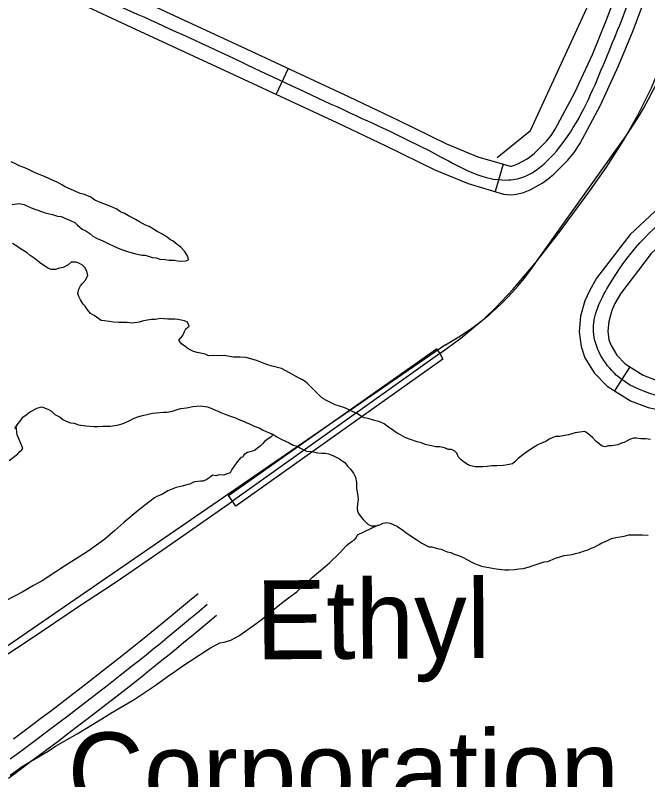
# Model space of a CAD drawing. Extents: x 3313442 to 3351311, y 721974 to 747360.
# Drawn here: x 3328533 to 3329198, y 728471 to 729274 of the extents above; entities that cross this region are included whole.
import ezdxf

# ---------------------------------------------------------------- set-up
doc = ezdxf.new("R2010")
doc.units = 0
for name, color, linetype in [('V-BLDG-IDEN', 7, 'Continuous'), ('V-BRDG-OTLN', 7, 'Continuous'), ('V-RAIL-TRAK', 7, 'Continuous'), ('V-ROAD-CNTR', 7, 'Continuous'), ('V-SITE-VEGE', 7, 'Continuous'), ('V-TOPO-SHOR', 7, 'Continuous')]:
    doc.layers.add(name, color=color, linetype=linetype)

msp = doc.modelspace()

# ---------------------------------------------------------------- linework, layer by layer
at = {"layer": 'V-BRDG-OTLN'}
msp.add_lwpolyline([(3328982.32, 728913.09), (3328764.87, 728758.35), (3328761.23, 728763.75), (3328757.11, 728769.52), (3328975.68, 728923.94), (3328979.32, 728918.99)], close=True, dxfattribs=at)
at = {"layer": 'V-RAIL-TRAK'}
msp.add_line((3328979.32, 728918.99), (3328761.23, 728763.76), dxfattribs=at)
for points in [[(3328979.32, 728918.99), (3329001.39, 728935.07), (3329016.57, 728947.61), (3329026.16, 728955.57), (3329038.06, 728967.39), (3329056.17, 728986.33), (3329079.87, 729014.34), (3329104.91, 729046.21), (3329137.15, 729090.04), (3329154.66, 729114.92), (3329172.31, 729142.82), (3329187.53, 729169.28), (3329201.92, 729198.04), (3329216.08, 729232.01), (3329229.4, 729270.58), (3329238.48, 729303.6)], [(3327828.49, 728090.38), (3327880.11, 728140.68), (3327961.34, 728211.22), (3327997.87, 728239.9), (3328025.79, 728262.33), (3328078.35, 728301.49), (3328164.14, 728361.84), (3328246.28, 728417.49), (3328326.61, 728470.48), (3328417.12, 728530.69), (3328505.94, 728590.8), (3328547.31, 728617.89), (3328600.33, 728653.66), (3328634.67, 728676.18), (3328652.15, 728687.99), (3328697.41, 728719.18), (3328761.23, 728763.76)]]:
    msp.add_lwpolyline(points, dxfattribs=at)
at = {"layer": 'V-ROAD-CNTR'}
for p, q in [((3328819.87, 729218.56), (3328807.25, 729191.35)), ((3329045.96, 729117.85), (3329037.42, 729089.09)), ((3329179.12, 728905.03), (3329163.16, 728879.63))]:
    msp.add_line(p, q, dxfattribs=at)
for points in [[(3328667.4, 729289.29), (3328775.65, 729239.08), (3328883.97, 729188.82), (3328935.41, 729164.18), (3328986.34, 729139.45), (3329019.31, 729125.76), (3329052.11, 729116.03), (3329053.78, 729115.86), (3329054.63, 729115.95), (3329057.88, 729116.8), (3329061.42, 729118.23), (3329071.11, 729123.45), (3329074.94, 729126.15), (3329078.84, 729129.43), (3329091.37, 729141.93), (3329096.31, 729148), (3329100.7, 729154.68), (3329121.32, 729193.34), (3329139.7, 729233.35), (3329154.59, 729269.47), (3329168.32, 729306.11)], [(3328598.87, 729287.96), (3328654.78, 729262.07), (3328763.02, 729211.87), (3328871.18, 729161.69), (3328922.38, 729137.16), (3328974.03, 729112.08), (3329009.26, 729097.45), (3329046.32, 729086.45), (3329053.82, 729085.71), (3329060, 729086.34), (3329067.35, 729088.28), (3329074.18, 729091.03), (3329086.91, 729097.89), (3329093.27, 729102.36), (3329099.13, 729107.3), (3329113.66, 729121.78), (3329120.55, 729130.25), (3329126.53, 729139.36), (3329148.21, 729180.01), (3329167.21, 729221.37), (3329182.51, 729258.49), (3329196.67, 729296.26)], [(3329081.07, 729015.7), (3329176.08, 729148.58)], [(3329293.2, 729122.75), (3329274.41, 729115.57), (3329247.16, 729101.4), (3329221.13, 729083.02), (3329179.4, 729044.06), (3329144.21, 728998.14), (3329136.56, 728984.84), (3329131.89, 728974.12), (3329127.33, 728958.11), (3329125.84, 728941.56), (3329127.89, 728926.32), (3329131.98, 728914.44), (3329141.45, 728898.63), (3329155.45, 728884.48), (3329179.68, 728869.25), (3329198.43, 728862.13), (3329224.9, 728856.49), (3329251.22, 728852.87), (3329323.89, 728846.16), (3329394.9, 728837.09), (3329432.04, 728828.42), (3329470.12, 728819.7), (3329513.88, 728810.63), (3329546.62, 728804.19)], [(3329303.92, 729094.73), (3329286.73, 729088.16), (3329262.81, 729075.72), (3329240.1, 729059.69), (3329201.7, 729023.84), (3329169.23, 728981.47), (3329163.4, 728971.32), (3329160.19, 728963.96), (3329156.95, 728952.61), (3329156.02, 728942.23), (3329157.22, 728933.28), (3329159.33, 728927.17), (3329165.32, 728917.15), (3329174.34, 728908.03), (3329193.11, 728896.24), (3329206.93, 728891), (3329230.07, 728886.06), (3329254.64, 728882.69), (3329327.17, 728875.99), (3329400.23, 728866.65), (3329438.8, 728857.65), (3329476.51, 728849.01), (3329519.82, 728840.04), (3329555.49, 728833.02)], [(3328985.23, 728928.08), (3327978.22, 728235.84)], [(3328725.08, 728666.38), (3328716.22, 728658.91), (3328707.62, 728651.72), (3328699.27, 728644.79), (3328691.16, 728638.11), (3328683.28, 728631.66), (3328675.63, 728625.43), (3328668.2, 728619.42), (3328660.99, 728613.62), (3328653.98, 728608.02), (3328647.19, 728602.61), (3328633.98, 728592.17), (3328621.56, 728582.43), (3328609.88, 728573.35), (3328598.89, 728564.87), (3328588.58, 728556.95), (3328578.88, 728549.55), (3328569.77, 728542.64), (3328561.22, 728536.18), (3328545.14, 728524.09), (3328531.04, 728513.56)], [(3328734.75, 728654.91), (3328725.86, 728647.42), (3328717.22, 728640.2), (3328708.83, 728633.23), (3328700.68, 728626.52), (3328692.76, 728620.04), (3328685.08, 728613.78), (3328677.62, 728607.75), (3328670.37, 728601.92), (3328663.34, 728596.29), (3328656.51, 728590.86), (3328643.26, 728580.38), (3328630.79, 728570.61), (3328619.06, 728561.49), (3328608.04, 728552.99), (3328597.69, 728545.04), (3328587.97, 728537.62), (3328578.83, 728530.68), (3328570.25, 728524.2), (3328554.14, 728512.08), (3328540, 728501.53), (3328527.6, 728492.33)], [(3328744.41, 728643.44), (3328735.5, 728635.93), (3328726.82, 728628.67), (3328718.39, 728621.67), (3328710.2, 728614.93), (3328702.25, 728608.42), (3328694.53, 728602.13), (3328687.03, 728596.07), (3328679.76, 728590.22), (3328672.7, 728584.57), (3328665.84, 728579.11), (3328652.53, 728568.59), (3328640.02, 728558.79), (3328628.25, 728549.64), (3328617.19, 728541.1), (3328606.81, 728533.13), (3328597.05, 728525.68), (3328587.89, 728518.72), (3328579.28, 728512.22), (3328563.13, 728500.08), (3328548.96, 728489.5), (3328536.53, 728480.28), (3328525.64, 728472.23)]]:
    msp.add_lwpolyline(points, dxfattribs=at)
for centre, radius, start, end in [((3328761.59, 729424.13), 497.73, 326.38346, 346.54947), ((3328854.96, 729166.81), 271.96, 298.62078, 326.24591)]:
    msp.add_arc(centre, radius, start, end, dxfattribs=at)
for points in [[(3326478.04, 730210.35), (3326482.35, 730403.29), (3326476.58, 730549.39), (3326473.61, 730637.71), (3326464.08, 730712.16), (3326370.96, 730713.71), (3326297.71, 730698.23), (3326169.71, 730725.9), (3326116.45, 730727.88), (3325982.64, 730689.67), (3325835.77, 730656.61), (3325666.24, 730661.4), (3325490.23, 730637.83), (3325403.5, 730634.84), (3325340.74, 730586.21), (3325201.43, 730523.99), (3325133.39, 730524.77), (3325012.9, 730513.46), (3324963.14, 730471.34), (3324981.93, 730365.88), (3324989.76, 730188.11), (3325009.72, 730055.84), (3325043.42, 729962.4), (3324997.98, 729812.51), (3325023.28, 729696.25), (3325064.51, 729608.4), (3325131.37, 729516.61), (3325150.36, 729377.77), (3325146.87, 729245.63), (3325126.45, 729132.53), (3325181.34, 729069.88), (3325338.87, 729062.31), (3325343.56, 728961.08), (3325372.85, 728878.06), (3325434.63, 728797.89), (3325537.34, 728748.77), (3325622.45, 728705.03), (3325714.6, 728675.45), (3325802.67, 728663.42), (3325976.26, 728695.07), (3326194.29, 728726.31), (3326466.63, 728765.32), (3326625.11, 728781.99), (3326781.78, 728849.74), (3326900.23, 728862.4), (3326981.75, 728872.83), (3327122.94, 728906.43), (3327349.99, 728934.63), (3327499.05, 728974.33), (3327515.65, 728986.69), (3327498, 729057.12), (3327490.77, 729119.3), (3327510.96, 729180.47), (3327588.76, 729283.84), (3327686.92, 729357.21), (3327753.03, 729377.43), (3327803.43, 729380.44), (3327847.87, 729388.87), (3327934.83, 729389.79), (3328039.14, 729390.23), (3328120.59, 729395.25), (3328249.21, 729403.96), (3328319.73, 729407.13), (3328384.24, 729401.49), (3328424.57, 729387.35), (3328470.08, 729368.59), (3328549.26, 729327.46), (3328661.09, 729275.68), (3328877.57, 729175.26), (3328980.19, 729125.77), (3329049.22, 729101.24), (3329067.8, 729104.63), (3329088.99, 729118.36), (3329113.61, 729147.02), (3329153.45, 729227.36), (3329182.49, 729301.19), (3329201.64, 729378.5), (3329199.66, 729471.18), (3329192.73, 729551.54), (3329166.92, 729646.66), (3329121.79, 729727.55), (3329091.49, 729778.71), (3329016.19, 729835.66), (3328941.73, 729880.13), (3328875.38, 729924.2), (3328789.67, 729967.9), (3328700.81, 730000.01), (3328643.56, 730009.51), (3328577.01, 730014.29), (3328435.19, 729993.91), (3328288.99, 729968.49), (3328169.46, 729944.48), (3328087.81, 729917.23), (3328042.9, 729880.41), (3327999.54, 729814.48), (3327967.22, 729727.08), (3328009.37, 729621.12)], [(3329560.48, 728816.75), (3329473.31, 728834.35), (3329397.56, 728851.87), (3329252.93, 728867.78), (3329164.89, 728896.25), (3329140.93, 728941.89), (3329156.72, 728989.8), (3329230.61, 729071.35), (3329298.56, 729108.74)]]:
    msp.add_spline(points, degree=3, dxfattribs=at)
at = {"layer": 'V-SITE-VEGE'}
for points in [[(3328535.25, 728813.2), (3328537.7, 728815.97), (3328539.44, 728817.36), (3328540.84, 728819.09), (3328539.81, 728821.88), (3328534.97, 728833.38), (3328533.8, 728842.32), (3328535.74, 728845.21), (3328539.16, 728849.17), (3328540.87, 728852), (3328544.28, 728854.26), (3328547.7, 728857.08), (3328550.54, 728858.78), (3328555.65, 728861.59), (3328560.76, 728862.71), (3328567, 728860.42), (3328570.96, 728858.14), (3328574.35, 728854.72), (3328580.02, 728851.87), (3328582.85, 728849.59), (3328586.24, 728847.87), (3328590.78, 728846.16), (3328594.75, 728845.58), (3328599.28, 728843.86), (3328607.22, 728842.7), (3328615.73, 728842.1), (3328619.7, 728842.09), (3328624.81, 728842.63), (3328629.34, 728842.62), (3328632.75, 728842.61), (3328640.13, 728843.72), (3328645.24, 728844.83), (3328652.62, 728848.21), (3328657.17, 728850.47), (3328661.71, 728852.15), (3328665.12, 728853.28), (3328672.5, 728854.95), (3328677.04, 728856.07), (3328681.02, 728856.62), (3328688.4, 728857.17), (3328692.37, 728857.16), (3328698.05, 728858.27), (3328703.16, 728859.95), (3328707.13, 728861.07), (3328712.81, 728861.62), (3328719.62, 728863.3), (3328727.56, 728863.84), (3328734.94, 728862.68), (3328739.47, 728860.96), (3328742.3, 728859.82), (3328746.27, 728858.1), (3328749.1, 728856.96), (3328754.2, 728854.67), (3328759.3, 728852.95), (3328764.4, 728851.23), (3328767.8, 728849.52), (3328773.46, 728847.23), (3328776.3, 728846.08), (3328779.13, 728844.94), (3328784.23, 728842.65), (3328789.89, 728840.36), (3328792.72, 728838.65), (3328797.25, 728836.37), (3328801.79, 728834.65), (3328802.4, 728834.4)], [(3328802.4, 728834.4), (3328803.29, 728832.6), (3328801.84, 728831.42), (3328795.21, 728826.57), (3328792.77, 728823.8), (3328790.32, 728821.37), (3328784.39, 728816.87), (3328777.08, 728814.8), (3328773.24, 728812.38), (3328772.19, 728809.95), (3328770.1, 728809.61), (3328766.26, 728805.1), (3328760.66, 728796.77), (3328758.91, 728793.29), (3328754.73, 728791.92), (3328752.29, 728790.88), (3328747.42, 728791.25), (3328743.94, 728790.21), (3328740.46, 728790.92), (3328734.18, 728786.42), (3328730.35, 728784.69), (3328727.91, 728784.7), (3328721.3, 728784.03), (3328718.86, 728782.99), (3328716.42, 728781.61), (3328714.33, 728781.27), (3328708.41, 728779.55), (3328702.14, 728778.18), (3328693.43, 728774.38), (3328687.85, 728770.92), (3328681.58, 728768.51), (3328679.14, 728767.12), (3328665.54, 728756.73), (3328662.05, 728753.96), (3328647.04, 728741.14), (3328637.62, 728732.82), (3328627.15, 728723.81), (3328609.36, 728711), (3328585.65, 728696.12), (3328575.53, 728689.54), (3328561.23, 728679.85), (3328552.17, 728675.01), (3328539.97, 728668.09), (3328524.63, 728659.79)], [(3328526.53, 728806.27), (3328535.25, 728813.2)], [(3328527.49, 728475.5), (3328540.05, 728484.85), (3328548.77, 728490.04), (3328567.59, 728500.76), (3328575.27, 728505.95), (3328597.93, 728519.1), (3328623.73, 728535.02), (3328633.49, 728540.9), (3328657.9, 728555.08), (3328671.5, 728564.43), (3328679.87, 728569.96), (3328692.78, 728579.31), (3328700.8, 728584.51), (3328709.17, 728590.39), (3328734.28, 728607.01), (3328738.11, 728609.43), (3328747.87, 728614.62), (3328752.4, 728615.3), (3328759.71, 728617.71), (3328768.08, 728622.2), (3328783.43, 728632.94), (3328792.84, 728639.86), (3328809.24, 728653.72), (3328820.06, 728662.04), (3328828.78, 728668.27), (3328831.22, 728670.35), (3328838.2, 728676.59), (3328845.18, 728683.52), (3328858.45, 728694.61), (3328863.33, 728698.77), (3328873.8, 728708.82), (3328877.3, 728712.99), (3328880.79, 728716.8), (3328883.23, 728718.88), (3328887.07, 728721.65), (3328889.51, 728723.04), (3328891.26, 728725.12), (3328892.66, 728728.24), (3328914.05, 728738.38), (3328916.06, 728738.94), (3328919.47, 728740.63), (3328923.44, 728741.19), (3328926.84, 728740.61), (3328929.68, 728739.46), (3328934.78, 728737.18), (3328940.44, 728733.19), (3328944.96, 728729.77), (3328947.79, 728728.05), (3328952.32, 728724.64), (3328955.15, 728722.92), (3328960.25, 728719.5), (3328967.6, 728715.51), (3328971.01, 728715.49), (3328976.68, 728713.77), (3328980.65, 728713.19), (3328986.88, 728710.33), (3328990.85, 728709.75), (3328994.25, 728708.04), (3328999.91, 728706.32), (3329003.88, 728704.6), (3329007.84, 728702.32), (3329012.37, 728700.03), (3329015.2, 728698.32), (3329018.6, 728697.17), (3329023.14, 728695.45), (3329032.77, 728693.72), (3329038.44, 728692.57), (3329047.52, 728691.4), (3329052.06, 728691.38), (3329058.3, 728691.93), (3329062.27, 728692.48), (3329066.81, 728693.03), (3329073.62, 728694.71), (3329076.47, 728695.84), (3329081.58, 728697.53), (3329088.96, 728699.77), (3329092.94, 728700.32), (3329100.89, 728703.7), (3329104.3, 728704.82), (3329109.98, 728706.5), (3329113.38, 728707.06), (3329118.49, 728707.61), (3329121.9, 728708.73), (3329126.44, 728709.85), (3329130.42, 728710.97), (3329134.96, 728712.66), (3329138.37, 728714.35), (3329141.78, 728715.47), (3329146.32, 728717.72), (3329149.74, 728719.98)], [(3329149.74, 728719.98), (3329154.28, 728721.67), (3329159.97, 728724.48), (3329164.51, 728725.6), (3329173.02, 728726.71), (3329178.13, 728728.4), (3329187.21, 728728.36), (3329192.32, 728728.35), (3329198.55, 728727.76)]]:
    msp.add_lwpolyline(points, dxfattribs=at)
at = {"layer": 'V-TOPO-SHOR'}
for points in [[(3329039.46, 729124.75), (3329074.8, 729153.34), (3329149.99, 729317.31), (3329162.14, 729386.82), (3329162.17, 729468.71), (3329151.85, 729553.02), (3329129.91, 729616.84), (3329086.32, 729704.83), (3329043.63, 729755.76), (3329008.26, 729791.33), (3328964.31, 729819.35), (3328917.76, 729847.97), (3328807.16, 729912.04), (3328690.73, 729957), (3328640.55, 729970.09), (3328595.12, 729968.43), (3328531.35, 729964.23), (3328419.34, 729952.19), (3328207.43, 729915.73), (3328162.39, 729909.87)], [(3328699.07, 729036.81), (3328696.24, 729038.52), (3328692.85, 729040.8), (3328687.75, 729044.22), (3328682.09, 729047.08), (3328679.26, 729048.79), (3328673.6, 729052.21), (3328669.63, 729053.93), (3328663.4, 729057.35), (3328659.44, 729059.64), (3328652.08, 729063.63), (3328647.55, 729065.92), (3328643.58, 729067.63), (3328639.62, 729070.48), (3328633.39, 729073.34), (3328628.86, 729075.06), (3328623.19, 729077.35), (3328616.39, 729080.21), (3328612.43, 729083.06), (3328605.63, 729085.92), (3328601.1, 729087.07), (3328594.87, 729089.93), (3328590.9, 729091.65), (3328585.24, 729093.93), (3328581.84, 729096.21), (3328576.74, 729099.07), (3328572.78, 729100.79), (3328568.81, 729102.5), (3328563.71, 729104.79), (3328556.35, 729107.65), (3328552.38, 729109.36), (3328546.72, 729112.22), (3328542.75, 729113.94), (3328537.09, 729116.22), (3328533.69, 729117.94), (3328528.59, 729120.23)], [(3328529.57, 729075.4), (3328536.95, 729076.51), (3328542.05, 729075.36), (3328549.42, 729071.93), (3328554.52, 729070.21), (3328561.32, 729067.92), (3328564.15, 729066.77), (3328568.68, 729065.62), (3328572.08, 729065.05), (3328577.19, 729063.33), (3328581.16, 729062.74), (3328586.82, 729060.46), (3328590.79, 729058.74), (3328595.32, 729056.45), (3328598.15, 729053.61), (3328603.24, 729049.62), (3328607.2, 729047.9), (3328611.16, 729045.05), (3328614.56, 729042.2), (3328619.65, 729039.35), (3328624.19, 729037.63), (3328629.85, 729034.78), (3328637.21, 729031.35), (3328642.88, 729029.06), (3328645.71, 729027.91), (3328650.81, 729026.2), (3328654.21, 729025.05), (3328658.18, 729023.9), (3328666.12, 729022.17), (3328669.52, 729022.16), (3328674.06, 729021.01), (3328676.89, 729019.86), (3328680.86, 729019.28), (3328684.83, 729018.13), (3328690.5, 729017.55), (3328694.47, 729016.97), (3328700.14, 729016.95), (3328703.54, 729016.37), (3328708.08, 729015.79), (3328712.05, 729016.34), (3328714.89, 729017.46), (3328714.33, 729020.87), (3328710.95, 729026.55), (3328706.99, 729030.54), (3328703.03, 729033.39), (3328699.07, 729036.81)], [(3328714.57, 728923.85), (3328711.18, 728926.7), (3328707.78, 728928.98), (3328704.96, 728932.96), (3328707.23, 728935.79), (3328709.51, 728938.62), (3328710.66, 728942.02), (3328712.37, 728944.85), (3328715.79, 728947.68), (3328714.1, 728951.66), (3328710.7, 728953.37), (3328703.9, 728954.53), (3328700.49, 728955.11), (3328696.52, 728955.12), (3328693.12, 728955.13), (3328685.75, 728955.72), (3328680.07, 728954.61), (3328676.1, 728954.62), (3328671.56, 728954.07), (3328666.45, 728952.95), (3328663.04, 728951.83), (3328655.66, 728950.72), (3328650.55, 728951.31), (3328646.02, 728951.32), (3328642.04, 728951.34), (3328635.81, 728951.92), (3328631.84, 728952.51), (3328626.73, 728953.09), (3328623.33, 728953.67), (3328615.97, 728958.8), (3328612.01, 728961.08), (3328609.19, 728964.5), (3328606.36, 728968.48), (3328604.1, 728970.76), (3328601.28, 728975.3), (3328599.59, 728978.71), (3328598.47, 728982.12), (3328599.62, 728986.66), (3328601.33, 728990.06), (3328603.61, 728992.32), (3328606.46, 728995.71), (3328609.31, 729000.81), (3328608.19, 729005.35), (3328605.94, 729009.33), (3328603.67, 729011.6), (3328599.71, 729013.89), (3328596.88, 729015.03), (3328591.77, 729015.05), (3328588.36, 729012.22), (3328583.24, 729009.41), (3328578.13, 729008.29), (3328575.29, 729007.17), (3328570.75, 729007.18), (3328567.92, 729008.32), (3328563.96, 729010.61), (3328558.3, 729014.6), (3328555.47, 729016.88), (3328551.51, 729019.73), (3328548.68, 729022.01), (3328545.28, 729024.85), (3328538.49, 729028.85), (3328535.66, 729031.13), (3328530, 729034.56)], [(3328892.48, 728855.73), (3328887.38, 728858.01), (3328883.98, 728859.73), (3328878.32, 728862.02), (3328869.25, 728864.88), (3328863.58, 728867.74), (3328860.19, 728869.45), (3328856.23, 728871.74), (3328852.83, 728874.58), (3328848.87, 728878.57), (3328845.48, 728881.98), (3328840.96, 728886.54), (3328838.7, 728888.82), (3328834.17, 728891.67), (3328830.77, 728893.38), (3328827.37, 728895.1), (3328821.14, 728898.52), (3328812.65, 728903.09), (3328808.68, 728904.24), (3328803.01, 728905.39), (3328796.21, 728907.69), (3328789.41, 728910.55), (3328785.44, 728911.7), (3328781.48, 728912.84), (3328775.81, 728914.56), (3328769, 728915.16), (3328762.2, 728915.18), (3328758.23, 728915.76), (3328752.56, 728916.92), (3328746.88, 728916.37), (3328741.78, 728916.95), (3328736.1, 728916.4), (3328732.7, 728918.12), (3328727.6, 728919.27), (3328724.2, 728919.85), (3328720.23, 728921), (3328714.57, 728923.85)], [(3328532.32, 728840.12), (3328535.74, 728845.21), (3328539.16, 728849.17), (3328540.87, 728852), (3328544.28, 728854.26), (3328547.7, 728857.08), (3328550.54, 728858.78), (3328555.65, 728861.59), (3328560.77, 728862.71), (3328567, 728860.42), (3328570.96, 728858.14), (3328574.35, 728854.72), (3328580.02, 728851.87), (3328582.85, 728849.59), (3328586.25, 728847.87), (3328590.78, 728846.16), (3328594.75, 728845.58), (3328599.28, 728843.86), (3328607.22, 728842.7), (3328615.73, 728842.1), (3328619.7, 728842.09), (3328624.81, 728842.63), (3328629.34, 728842.62), (3328632.75, 728842.61), (3328640.13, 728843.72), (3328645.24, 728844.83), (3328652.62, 728848.21), (3328657.17, 728850.47), (3328661.72, 728852.15), (3328665.12, 728853.28), (3328672.5, 728854.95), (3328677.04, 728856.07), (3328681.02, 728856.62), (3328688.4, 728857.17), (3328692.37, 728857.15), (3328698.05, 728858.27), (3328703.16, 728859.95), (3328707.13, 728861.07), (3328712.81, 728861.62), (3328719.62, 728863.3), (3328727.56, 728863.84), (3328734.94, 728862.68), (3328739.47, 728860.96), (3328742.3, 728859.82), (3328746.27, 728858.1), (3328749.1, 728856.96), (3328754.2, 728854.67), (3328759.3, 728852.95), (3328764.4, 728851.23)], [(3328764.4, 728851.23), (3328767.8, 728849.52), (3328773.46, 728847.23), (3328776.3, 728846.08), (3328779.13, 728844.94), (3328784.23, 728842.65), (3328789.89, 728840.36), (3328792.72, 728838.65), (3328797.25, 728836.37), (3328801.79, 728834.65), (3328804.62, 728833.5), (3328808.02, 728831.22), (3328813.11, 728828.37), (3328817.08, 728826.65), (3328821.04, 728824.94), (3328825.01, 728822.65), (3328829.54, 728821.51), (3328832.94, 728819.22), (3328835.77, 728818.08), (3328839.17, 728816.36), (3328844.27, 728815.78), (3328851.08, 728814.62), (3328855.05, 728814.04), (3328859.02, 728814.03), (3328862.42, 728813.45), (3328866.95, 728811.73), (3328870.35, 728810.02), (3328873.75, 728808.3), (3328876.58, 728806.02), (3328879.41, 728804.31), (3328882.23, 728800.33), (3328885.06, 728797.48), (3328888.45, 728792.94), (3328890.7, 728788.96), (3328891.82, 728783.28), (3328891.79, 728777.04), (3328892.91, 728771.36)], [(3329166.39, 728823.01), (3329160.15, 728821.9), (3329156.74, 728821.91), (3329153.33, 728820.79), (3329149.37, 728821.94), (3329146.54, 728824.21), (3329143.71, 728826.49), (3329139.75, 728830.48), (3329135.23, 728834.46), (3329131.83, 728836.75), (3329126.72, 728836.2), (3329121.62, 728835.65), (3329114.8, 728833.4), (3329110.82, 728832.85), (3329105.15, 728831.73), (3329101.18, 728831.74), (3329098.33, 728830.62), (3329094.36, 728828.93), (3329091.51, 728826.67), (3329086.97, 728824.99), (3329082.42, 728822.73), (3329079.58, 728821.04), (3329075.03, 728818.22), (3329071.62, 728815.96), (3329065.37, 728811.45), (3329061.38, 728808.05), (3329058.53, 728805.23), (3329055.69, 728802.97), (3329050.58, 728801.85), (3329046.04, 728801.3), (3329039.23, 728800.76), (3329034.12, 728800.77), (3329029.02, 728800.22), (3329024.48, 728799.67), (3329020.5, 728799.69), (3329016.53, 728799.7), (3329012, 728800.85), (3329009.16, 728801.99), (3329005.2, 728804.28), (3329001.81, 728807.13), (3328998.98, 728809.97), (3328997.29, 728813.95), (3328995.03, 728816.23), (3328991.63, 728817.94), (3328988.23, 728817.95), (3328984.26, 728819.67), (3328979.16, 728820.82), (3328974.62, 728820.83), (3328970.66, 728821.98), (3328963.85, 728823.14), (3328959.88, 728824.86), (3328955.35, 728826.01), (3328947.42, 728828.87), (3328942.89, 728830.59), (3328937.79, 728833.44), (3328934.39, 728835.16), (3328930.99, 728837.44), (3328925.33, 728841.43), (3328920.81, 728844.85), (3328916.28, 728847.13), (3328910.61, 728848.29), (3328903.81, 728850.58), (3328899.84, 728851.16), (3328895.87, 728853.45), (3328892.48, 728855.73)], [(3329201.02, 728828.57), (3329195.91, 728829.15), (3329190.81, 728829.17), (3329186.27, 728829.75), (3329182.87, 728829.76), (3329178.89, 728828.64), (3329173.77, 728825.82), (3329170.37, 728824.7), (3329166.39, 728823.01)], [(3328892.91, 728771.36), (3328893.46, 728765.69), (3328892.87, 728760.58), (3328892.29, 728756.61), (3328892.85, 728752.64), (3328894.54, 728749.8), (3328896.8, 728746.39), (3328899.06, 728744.11), (3328903.58, 728739.55), (3328906.98, 728737.84), (3328912.08, 728737.82), (3328916.06, 728738.94), (3328919.47, 728740.63), (3328923.44, 728741.19), (3328926.84, 728740.61), (3328929.68, 728739.46), (3328934.78, 728737.18), (3328940.44, 728733.19), (3328944.96, 728729.77), (3328947.79, 728728.05), (3328952.32, 728724.63), (3328955.15, 728722.92), (3328960.25, 728719.5), (3328967.6, 728715.5), (3328971.01, 728715.49), (3328976.68, 728713.77), (3328980.65, 728713.19), (3328986.88, 728710.33), (3328990.85, 728709.75), (3328994.25, 728708.04), (3328999.91, 728706.32), (3329003.88, 728704.6), (3329007.84, 728702.32), (3329012.37, 728700.03), (3329015.2, 728698.32), (3329018.6, 728697.17), (3329023.14, 728695.45), (3329032.77, 728693.72), (3329038.44, 728692.57), (3329047.52, 728691.4), (3329052.06, 728691.38), (3329058.3, 728691.93), (3329062.27, 728692.48), (3329066.81, 728693.03), (3329073.63, 728694.71), (3329076.47, 728695.84), (3329081.58, 728697.52), (3329088.96, 728699.77), (3329092.94, 728700.32), (3329100.89, 728703.7), (3329104.3, 728704.82), (3329109.98, 728706.5), (3329113.38, 728707.06), (3329118.49, 728707.61), (3329121.9, 728708.73), (3329126.44, 728709.85), (3329130.42, 728710.97), (3329134.96, 728712.66), (3329138.37, 728714.35), (3329141.78, 728715.47), (3329146.33, 728717.72), (3329149.74, 728719.98), (3329154.28, 728721.67), (3329159.97, 728724.48), (3329164.51, 728725.6)], [(3329164.51, 728725.6), (3329173.02, 728726.71), (3329178.13, 728728.39), (3329187.21, 728728.36), (3329192.32, 728728.34), (3329198.56, 728727.76)]]:
    msp.add_lwpolyline(points, dxfattribs=at)

# ---------------------------------------------------------------- texts
at = {"layer": 'V-BLDG-IDEN'}
for s, height, p in [('Ethyl', 83, (3328785.93, 728597.36)), ('Corporation', 82.9998, (3328588.16, 728437.27))]:
    msp.add_text(s, height=height, rotation=0.31789, dxfattribs=at).set_placement(p)

doc.saveas('drawing.dxf')
